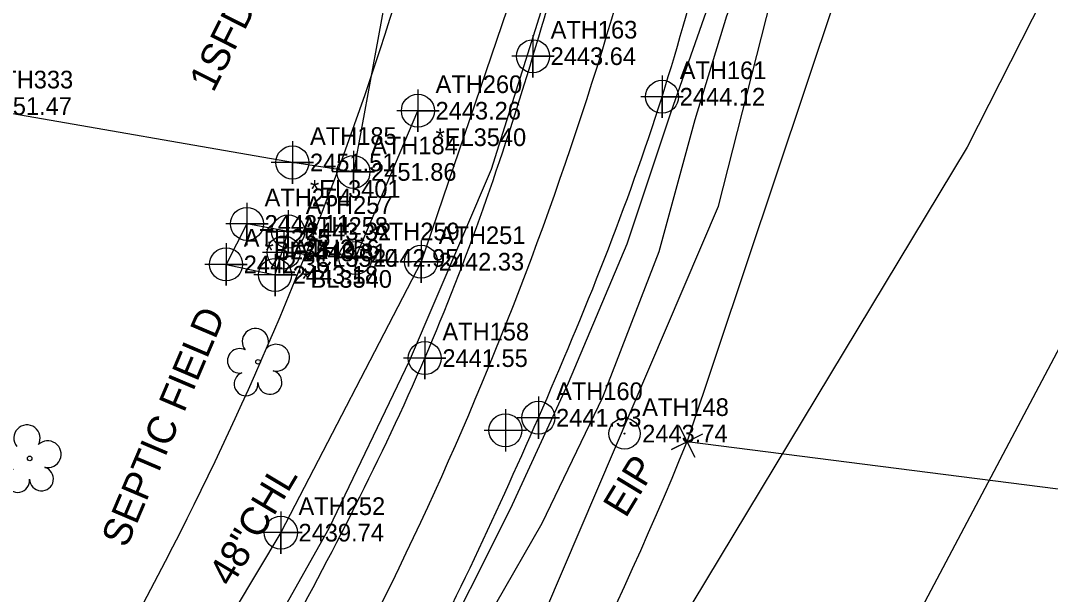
# Model space of a CAD drawing. Extents: x 983976 to 986421, y 758828 to 761458.
# Drawn here: x 984833.7 to 984979.4, y 760189.2 to 760270.5 of the extents above; entities that cross this region are included whole.
import ezdxf

# ---------------------------------------------------------------- set-up
doc = ezdxf.new("R2010")
doc.units = 0
for name, color, linetype in [('COGO Default Chain', 7, 'Continuous'), ('COGO Default Curve', 7, 'Continuous'), ('Exist Building', 7, 'Continuous'), ('Exist Building Text', 7, 'Continuous'), ('Exist DTM Crownline', 7, 'Continuous'), ('Exist DTM Drainline Cogo Point CELL', 7, 'Continuous'), ('Exist DTM Regular Point CELL', 7, 'Continuous'), ('Exist Horizontal Alignment', 7, 'Continuous'), ('Exist Other Culture Fence Line', 7, 'Continuous'), ('Exist Other Culture Fence Line Cogo Elevation', 7, 'Continuous'), ('Exist Other Culture Fence Line Cogo Number', 7, 'Continuous'), ('Exist Other Culture Fence Line Cogo Point CELL', 7, 'Continuous'), ('Exist Other Culture Fence Line Text', 7, 'Continuous'), ('Exist Property Corner CELL', 7, 'Continuous'), ('Exist Property Iron Pin CELL', 7, 'Continuous'), ('Exist Property Iron Pin Cogo Elevation', 7, 'Continuous'), ('Exist Property Iron Pin Cogo Number', 7, 'Continuous'), ('Exist Property Iron Pin Text', 7, 'Continuous'), ('Exist Property Line', 7, 'Continuous'), ('Exist Right of Way Line', 7, 'Continuous'), ('Exist Roads EOP', 7, 'Continuous'), ('Exist Roads EOP Cogo Point CELL', 7, 'Continuous'), ('Exist Roads EOP Other', 7, 'Continuous'), ('Exist Structure Major Bridge WW Cogo Point CELL', 7, 'Continuous'), ('Exist Utilities Sanitary Sewer UG Line', 7, 'Continuous'), ('Exist Utilities Sanitary Sewer UG Line Cogo Comment', 7, 'Continuous'), ('Exist Utilities Sanitary Sewer UG Line Cogo Elevation', 7, 'Continuous'), ('Exist Utilities Sanitary Sewer UG Line Cogo Number', 7, 'Continuous'), ('Exist Utilities Sanitary Sewer UG Line Cogo Point CELL', 7, 'Continuous'), ('Exist Utilities Sanitary Sewer UG Line Text', 7, 'Continuous'), ('Exist Utilities Telephone UG Cable SUE LOS C', 7, 'Continuous'), ('Exist Utilities Telephone UG FO SUE LOS B', 7, 'Continuous'), ('Exist Vegetation Tree CELL', 7, 'Continuous'), ('Exist Vegetation Woods Line', 7, 'Continuous')]:
    doc.layers.add(name, color=color, linetype=linetype)

msp = doc.modelspace()

# ---------------------------------------------------------------- linework, layer by layer
at = {"layer": 'COGO Default Chain'}
msp.add_arc((984418.15, 760419.36), 520.87, 328.4601, 345.2561, dxfattribs=at)
at = {"layer": 'COGO Default Curve'}
msp.add_arc((984418.15, 760419.36), 520.87, 328.4601, 345.2561, dxfattribs=at)
at = {"layer": 'Exist Building'}
msp.add_line((984872.14, 760250.36), (984826.35, 760258.35), dxfattribs=at)
msp.add_lwpolyline([(984885.49, 760274.77), (984880.79, 760249.02), (984872.14, 760250.36)], dxfattribs=at)
at = {"layer": 'Exist Horizontal Alignment'}
msp.add_arc((984418.15, 760419.36), 520.87, 328.4601, 345.2561, dxfattribs=at)
at = {"layer": 'Exist Other Culture Fence Line'}
msp.add_lwpolyline([(984902.51, 760285.25), (984904.87, 760278.9), (984890.36, 760236.31), (984870.51, 760197.95), (984840.66, 760148.02), (984831.85, 760170.26)], dxfattribs=at)
at = {"layer": 'Exist Other Culture Fence Line Cogo Point CELL'}
for points in [[(984890.36, 760239.31), (984890.36, 760233.31), (984890.36, 760236.31), (984893.36, 760236.31), (984887.36, 760236.31)], [(984870.51, 760200.95), (984870.51, 760194.95), (984870.51, 760197.95), (984873.51, 760197.95), (984867.51, 760197.95)]]:
    msp.add_lwpolyline(points, dxfattribs=at)
for centre in [(984890.36, 760236.31), (984870.51, 760197.95)]:
    msp.add_circle(centre, 2.34, dxfattribs=at)
at = {"layer": 'Exist Property Corner CELL'}
msp.add_line((984928.03, 760210.83), (984928.03, 760210.83), dxfattribs=at)
msp.add_lwpolyline([(984929.14, 760208.6), (984926.91, 760213.07), (984928.03, 760210.83), (984925.79, 760209.72), (984930.26, 760211.95)], dxfattribs=at)
at = {"layer": 'Exist Property Iron Pin CELL'}
for radius in [2.2, 0.0707]:
    msp.add_circle((984919.16, 760211.97), radius, dxfattribs=at)
at = {"layer": 'Exist Property Line'}
msp.add_line((985486.15, 760139.25), (984928.03, 760210.83), dxfattribs=at)
at = {"layer": 'Exist Right of Way Line'}
msp.add_line((984928.03, 760210.83), (984950.88, 760279.17), dxfattribs=at)
for radius, end in [(490.87, 345.2561), (550.87, 337.7566)]:
    msp.add_arc((984418.15, 760419.36), radius, 328.4601, end, dxfattribs=at)
at = {"layer": 'Exist Roads EOP'}
for points in [[(984848.52, 760141.85), (984870.29, 760181.25), (984890.88, 760222.66), (984906.2, 760265.41), (984918.1, 760309.21)], [(984863.71, 760131.91), (984886.81, 760172.15), (984906.97, 760214.22), (984924.47, 760259.67), (984936.56, 760305.94)]]:
    msp.add_spline(points, degree=3, dxfattribs=at)
at = {"layer": 'Exist Roads EOP Cogo Point CELL'}
for points in [[(984906.2, 760268.41), (984906.2, 760262.41), (984906.2, 760265.41), (984909.2, 760265.41), (984903.2, 760265.41)], [(984924.47, 760262.67), (984924.47, 760256.67), (984924.47, 760259.67), (984927.47, 760259.67), (984921.47, 760259.67)], [(984890.88, 760225.66), (984890.88, 760219.66), (984890.88, 760222.66), (984893.88, 760222.66), (984887.88, 760222.66)], [(984906.97, 760217.22), (984906.97, 760211.22), (984906.97, 760214.22), (984909.97, 760214.22), (984903.97, 760214.22)]]:
    msp.add_lwpolyline(points, dxfattribs=at)
for centre in [(984906.2, 760265.41), (984924.47, 760259.67), (984890.88, 760222.66), (984906.97, 760214.22)]:
    msp.add_circle(centre, 2.34, dxfattribs=at)
at = {"layer": 'Exist Roads EOP Other'}
for points in [[(984902.3, 760215.44), (984902.3, 760212.44)], [(984899.3, 760212.44), (984902.3, 760212.44)], [(984902.3, 760212.44), (984905.3, 760212.44)], [(984902.3, 760212.44), (984902.3, 760209.44)]]:
    msp.add_lwpolyline(points, dxfattribs=at)
msp.add_circle((984902.3, 760212.44), 2.34, dxfattribs=at)
at = {"layer": 'Exist Structure Major Bridge WW Cogo Point CELL'}
for points in [[(984872.14, 760253.36), (984872.14, 760247.36), (984872.14, 760250.36), (984875.14, 760250.36), (984869.14, 760250.36)], [(984880.79, 760252.02), (984880.79, 760246.02), (984880.79, 760249.02), (984883.79, 760249.02), (984877.79, 760249.02)]]:
    msp.add_lwpolyline(points, dxfattribs=at)
for centre in [(984872.14, 760250.36), (984880.79, 760249.02)]:
    msp.add_circle(centre, 2.34, dxfattribs=at)
at = {"layer": 'Exist Utilities Sanitary Sewer UG Line'}
for points in [[(984870.91, 760237.62), (984881.06, 760236.84), (984889.91, 760257.69)], [(984865.71, 760241.66), (984862.76, 760235.94), (984869.69, 760234.45), (984871.55, 760240.59), (984865.71, 760241.66)]]:
    msp.add_lwpolyline(points, dxfattribs=at)
at = {"layer": 'Exist Utilities Sanitary Sewer UG Line Cogo Point CELL'}
for points in [[(984889.91, 760260.69), (984889.91, 760254.69), (984889.91, 760257.69), (984892.91, 760257.69), (984886.91, 760257.69)], [(984865.71, 760244.66), (984865.71, 760238.66), (984865.71, 760241.66), (984868.71, 760241.66), (984862.71, 760241.66)], [(984871.55, 760243.59), (984871.55, 760237.59), (984871.55, 760240.59), (984874.55, 760240.59), (984868.55, 760240.59)], [(984870.91, 760240.62), (984870.91, 760234.62), (984870.91, 760237.62), (984873.91, 760237.62), (984867.91, 760237.62)], [(984862.76, 760238.94), (984862.76, 760232.94), (984862.76, 760235.94), (984865.76, 760235.94), (984859.76, 760235.94)], [(984881.06, 760239.84), (984881.06, 760233.84), (984881.06, 760236.84), (984884.06, 760236.84), (984878.06, 760236.84)], [(984869.69, 760237.45), (984869.69, 760231.45), (984869.69, 760234.45), (984872.69, 760234.45), (984866.69, 760234.45)]]:
    msp.add_lwpolyline(points, dxfattribs=at)
for centre in [(984889.91, 760257.69), (984865.71, 760241.66), (984871.55, 760240.59), (984870.91, 760237.62), (984881.06, 760236.84), (984862.76, 760235.94), (984869.69, 760234.45)]:
    msp.add_circle(centre, 2.34, dxfattribs=at)
at = {"layer": 'Exist Utilities Telephone UG Cable SUE LOS C'}
for points in [[(984839.82, 760146.02), (984841.69, 760142.76), (984844.47, 760145.95), (984847.71, 760147.53), (984863.16, 760173.34), (984877.34, 760198.57), (984888.72, 760222.26), (984900.32, 760249.43), (984908.44, 760275.25), (984915.7, 760304.53), (984921.73, 760332.28), (984927.8, 760354.66), (984933.35, 760371.93), (984940.54, 760390.54), (984946.6, 760405.86)], [(984850.54, 760091.66), (984850.63, 760097.64), (984859.64, 760114.61), (984864.14, 760121.69), (984870.98, 760135.65), (984883.31, 760156.93), (984894.36, 760176.43), (984907.48, 760199.31), (984916.1, 760217.14), (984924.08, 760237.74), (984929.15, 760256.45), (984933.62, 760271.11), (984938.95, 760285.27), (984944.26, 760311.94), (984949.82, 760340.51), (984962.19, 760379.55), (984968.58, 760393.24)]]:
    msp.add_lwpolyline(points, dxfattribs=at)
at = {"layer": 'Exist Utilities Telephone UG FO SUE LOS B'}
msp.add_lwpolyline([(984866.61, 760116.12), (984863.84, 760117.08), (984860.35, 760119.38), (984860.34, 760123.48), (984867.88, 760137.67), (984880.51, 760158.38), (984891.65, 760178.65), (984903.04, 760201.33), (984911.22, 760219.14), (984919.53, 760238.85), (984925.78, 760257.53), (984931.03, 760272.57), (984935.49, 760286.55), (984940.38, 760312.87), (984946.87, 760341.41), (984959.36, 760380.23), (984965.58, 760395.13)], dxfattribs=at)
at = {"layer": 'Exist Vegetation Tree CELL'}
for p, q in [((984867.29, 760222.13), (984867.29, 760222.13)), ((984834.96, 760208.46), (984834.96, 760208.46))]:
    msp.add_line(p, q, dxfattribs=at)
for centre in [(984867.29, 760222.13), (984834.96, 760208.46)]:
    msp.add_circle(centre, 0.326, dxfattribs=at)
for centre, radius, start, end in [((984866.91, 760225), 1.86, 330.1651, 219.7134), ((984864.69, 760222.28), 1.73, 62.6636, 279.3457), ((984869.84, 760222.72), 1.9, 257.1011, 134.1999), ((984865.59, 760219.01), 1.69, 111.5671, 6.231), ((984868.96, 760219.23), 1.7, 181.2822, 74.56), ((984834.57, 760211.34), 1.86, 330.1651, 219.7134), ((984837.51, 760209.05), 1.9, 257.1011, 134.1999), ((984833.25, 760205.34), 1.69, 111.5671, 6.231), ((984836.63, 760205.57), 1.7, 181.2822, 74.56)]:
    msp.add_arc(centre, radius, start, end, dxfattribs=at)
at = {"layer": 'Exist Vegetation Woods Line'}
msp.add_line((985008.58, 760333.06), (984967.64, 760252.53), dxfattribs=at)
for points in [[(984967.64, 760252.53), (984854.89, 760065.43), (984854.89, 760090.28), (984898.18, 760163.89), (984932.46, 760244.19), (984956.17, 760337.55)], [(984902.49, 760095.82), (984939.65, 760146.48), (984981.66, 760225.9)]]:
    msp.add_lwpolyline(points, dxfattribs=at)

# ---------------------------------------------------------------- texts
at = {"layer": 'Exist Building Text'}
msp.add_text('1SFD', height=4, rotation=63.2641, dxfattribs=at).set_placement((984860.94, 760260.15))
at = {"layer": 'Exist DTM Crownline'}
for s, p in [('2451.47', (984828.85, 760257.1)), ('2451.51', (984874.64, 760249.11)), ('2451.86', (984883.29, 760247.77)), ('*EL3401', (984874.64, 760245.36))]:
    msp.add_text(s, height=2.5, dxfattribs=at).set_placement(p)
at = {"layer": 'Exist DTM Drainline Cogo Point CELL'}
for s, p in [('2443.64', (984908.7, 760264.16)), ('2444.12', (984926.97, 760258.42)), ('2441.55', (984893.38, 760221.41)), ('2441.93', (984909.47, 760212.97))]:
    msp.add_text(s, height=2.5, dxfattribs=at).set_placement(p)
at = {"layer": 'Exist DTM Regular Point CELL'}
for s, p in [('ATH163', (984908.7, 760267.91)), ('ATH161', (984926.97, 760262.17)), ('ATH158', (984893.38, 760225.16)), ('ATH160', (984909.47, 760216.72))]:
    msp.add_text(s, height=2.5, dxfattribs=at).set_placement(p)
at = {"layer": 'Exist Other Culture Fence Line Cogo Elevation'}
for s, p in [('2442.33', (984892.86, 760235.06)), ('2439.74', (984873.01, 760196.7))]:
    msp.add_text(s, height=2.5, dxfattribs=at).set_placement(p)
at = {"layer": 'Exist Other Culture Fence Line Cogo Number'}
for s, p in [('ATH251', (984892.86, 760238.81)), ('ATH252', (984873.01, 760200.45))]:
    msp.add_text(s, height=2.5, dxfattribs=at).set_placement(p)
at = {"layer": 'Exist Other Culture Fence Line Text'}
msp.add_text('48"CHL', height=4, rotation=59.1303, dxfattribs=at).set_placement((984863.49, 760190.11))
at = {"layer": 'Exist Property Iron Pin Cogo Elevation'}
msp.add_text('2443.74', height=2.5, dxfattribs=at).set_placement((984921.66, 760210.72))
at = {"layer": 'Exist Property Iron Pin Cogo Number'}
msp.add_text('ATH148', height=2.5, dxfattribs=at).set_placement((984921.66, 760214.47))
at = {"layer": 'Exist Property Iron Pin Text'}
msp.add_text('EIP', height=4, rotation=58.6838, dxfattribs=at).set_placement((984919.33, 760199.89))
at = {"layer": 'Exist Roads EOP'}
for s, p in [('ATH333', (984828.85, 760260.85)), ('ATH185', (984874.64, 760252.86)), ('ATH184', (984883.29, 760251.52))]:
    msp.add_text(s, height=2.5, dxfattribs=at).set_placement(p)
at = {"layer": 'Exist Utilities Sanitary Sewer UG Line Cogo Comment'}
for s, p in [('*EL3540', (984892.41, 760252.69)), ('*BL3540', (984868.21, 760236.66)), ('*CL3540', (984874.05, 760235.59)), ('*BL3540', (984873.41, 760232.62))]:
    msp.add_text(s, height=2.5, dxfattribs=at).set_placement(p)
at = {"layer": 'Exist Utilities Sanitary Sewer UG Line Cogo Elevation'}
for s, p in [('2443.26', (984892.41, 760256.44)), ('2443.11', (984868.21, 760240.41)), ('2443.32', (984874.05, 760239.34)), ('2443.31', (984873.41, 760236.37)), ('2442.36', (984865.26, 760234.69)), ('2442.95', (984883.56, 760235.59)), ('2443.18', (984872.19, 760233.2))]:
    msp.add_text(s, height=2.5, dxfattribs=at).set_placement(p)
at = {"layer": 'Exist Utilities Sanitary Sewer UG Line Cogo Number'}
for s, p in [('ATH260', (984892.41, 760260.19)), ('ATH254', (984868.21, 760244.16)), ('ATH257', (984874.05, 760243.09)), ('ATH258', (984873.41, 760240.12)), ('ATH259', (984883.56, 760239.34)), ('ATH255', (984865.26, 760238.44)), ('ATH256', (984872.19, 760236.95))]:
    msp.add_text(s, height=2.5, dxfattribs=at).set_placement(p)
at = {"layer": 'Exist Utilities Sanitary Sewer UG Line Text'}
msp.add_text('SEPTIC FIELD', height=4, rotation=66.9895, dxfattribs=at).set_placement((984848.66, 760195.66))

doc.saveas('drawing.dxf')
